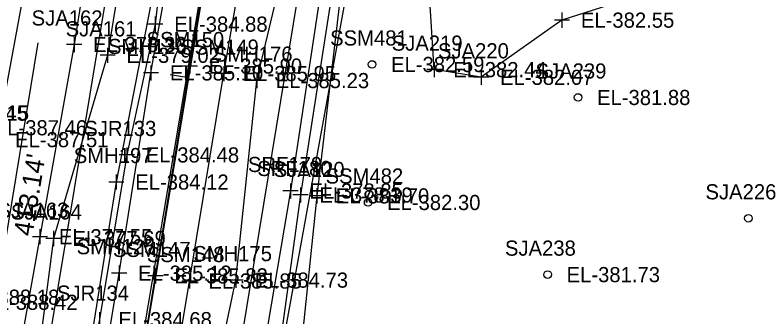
# Model space of a CAD drawing. Extents: x 1189978 to 1314812, y 571533 to 629339.
# Drawn here: x 1217588.4 to 1217785.8, y 621960.6 to 622040.1 of the extents above; entities that cross this region are included whole.
import ezdxf

# ---------------------------------------------------------------- set-up
doc = ezdxf.new("R2010")
doc.units = 0
for name, color, linetype in [('SURVEY - CENTERLINE - Preliminary', 7, 'Continuous'), ('SURVEY - CENTERLINE - Preliminary Text', 7, 'Continuous'), ('SURVEY - DRAINAGE - Area Shapes', 7, 'Continuous'), ('SURVEY - DTM - Breaklines', 7, 'Continuous'), ('SURVEY - DTM - Breaklines - Points - Elevations', 7, 'Continuous'), ('SURVEY - DTM - Breaklines - Points - Locators', 7, 'Continuous'), ('SURVEY - DTM - Breaklines - Points - Numbers', 7, 'Continuous'), ('SURVEY - DTM - Spot Points - Elevations', 7, 'Continuous'), ('SURVEY - DTM - Spot Points - Locators', 7, 'Continuous'), ('SURVEY - DTM - Spot Points - Point Numbers', 7, 'Continuous'), ('SURVEY - PROPERTY - ROW Lines', 7, 'Continuous'), ('SURVEY - PROPERTY - ROW Lines Text', 7, 'Continuous'), ('SURVEY - TRANSPORTATION - Roads', 7, 'Continuous'), ('SURVEY - TRANSPORTATION - Roads - Points - Elevations', 7, 'Continuous'), ('SURVEY - TRANSPORTATION - Roads - Points - Locators', 7, 'Continuous'), ('SURVEY - TRANSPORTATION - Roads - Points - Numbers', 7, 'Continuous'), ('SURVEY - UTILITIES - Electric (Overhead) with Text', 7, 'Continuous'), ('SURVEY - VEGETATION - Features - Points - Elevations', 7, 'Continuous'), ('SURVEY - VEGETATION - Features - Points - Locators', 7, 'Continuous'), ('SURVEY - VEGETATION - Features - Points - Numbers', 7, 'Continuous'), ('SURVEY - VEGETATION - Features with Text', 7, 'Continuous')]:
    doc.layers.add(name, color=color, linetype=linetype)

msp = doc.modelspace()

# ---------------------------------------------------------------- linework, layer by layer
at = {"layer": 'SURVEY - CENTERLINE - Preliminary'}
msp.add_line((1217525.37, 621363.65), (1217649.69, 622116.55), dxfattribs=at)
msp.add_line((1217525.37, 621363.65), (1217649.69, 622116.55), dxfattribs=at)
at = {"layer": 'SURVEY - CENTERLINE - Preliminary Text'}
msp.add_line((1217634.33, 622023.52), (1217629.4, 622024.34), dxfattribs=at)
at = {"layer": 'SURVEY - DRAINAGE - Area Shapes'}
msp.add_line((1217415.87, 620731.68), (1218149.36, 625079.9), dxfattribs=at)
at = {"layer": 'SURVEY - DTM - Breaklines'}
for points in [[(1217591.74, 621765.73), (1217601.34, 621822.74), (1217608.84, 621869.52), (1217625.54, 621971.19), (1217634.6, 622026.63), (1217643.17, 622076.74), (1217651.21, 622124.47), (1217659.56, 622173.57), (1217668.17, 622224.78), (1217678.08, 622282.54), (1217688.16, 622340.37), (1217697.26, 622392.62), (1217705.46, 622440.01), (1217714.49, 622490.86), (1217723.28, 622541.33), (1217731.44, 622588.51), (1217739.96, 622637.78), (1217748.52, 622688.04), (1217748.57, 622688.21), (1217756.95, 622738.51)], [(1217685.05, 622529.18), (1217678.55, 622499.44), (1217670.66, 622464.16), (1217662, 622418.29), (1217653.65, 622375.31), (1217647.46, 622326.5), (1217637.7, 622278.06), (1217624.97, 622233.51), (1217617.77, 622187.81), (1217609.29, 622147.05), (1217599.66, 622101.36), (1217592.56, 622056.45), (1217583.44, 622007.19), (1217575.28, 621964.22), (1217564.77, 621919.14), (1217554.54, 621865.01), (1217546.46, 621821.67), (1217537.02, 621781.08), (1217528.09, 621784.53), (1217517.71, 621784.08)], [(1217696.43, 622511.42), (1217690.45, 622501.14), (1217682.75, 622461.47), (1217672.56, 622421.42), (1217668.77, 622381.8), (1217659.15, 622328.76), (1217653.09, 622287.28), (1217639.42, 622228.14), (1217631.31, 622175.39), (1217620.6, 622119.17), (1217610.69, 622074.17), (1217604.05, 622032.34), (1217595.02, 621981.54), (1217586.73, 621935.16), (1217578.82, 621892.7), (1217571.48, 621848.7), (1217561.74, 621801.1), (1217546.07, 621743.68), (1217517.89, 621741.61)], [(1217697.46, 622510.95), (1217695.23, 622500.63), (1217687.54, 622460.4), (1217680.36, 622419.79), (1217673.4, 622382.01), (1217663.19, 622329.29), (1217655.83, 622286.39), (1217645.17, 622227.36), (1217637.36, 622175.23), (1217627.75, 622118.91), (1217619.76, 622071.57), (1217612.88, 622029.47), (1217598.58, 621981.08), (1217592.58, 621934.99), (1217582.82, 621892.2), (1217576.26, 621849.18), (1217566.85, 621799.58), (1217549.42, 621742.26), (1217567.14, 621728.67)], [(1217704.42, 622509.33), (1217700.3, 622496.16), (1217691.81, 622446.34), (1217683.59, 622396.11), (1217675.05, 622345.79), (1217666.22, 622294.23), (1217657.54, 622241.9), (1217648.88, 622192.24), (1217640.73, 622142.53), (1217632.56, 622094.35), (1217625.38, 622048.54), (1217615.19, 621995.99), (1217607.27, 621946.79), (1217598.3, 621895.28), (1217589.38, 621843.86), (1217580.22, 621794.45), (1217573.72, 621781.31), (1217574.43, 621774.4), (1217580.6, 621768.52)], [(1217604.56, 621765.51), (1217608.59, 621775.31), (1217618.98, 621822.73), (1217628.13, 621872.31), (1217636.41, 621920.88), (1217646.75, 621970.08), (1217652.31, 622022.79), (1217663.53, 622069.73), (1217672.49, 622118.54), (1217678.26, 622168.97), (1217683.24, 622219.55), (1217691.94, 622272.25), (1217701.2, 622320.93), (1217709.61, 622368.48), (1217718.57, 622415.45), (1217724.25, 622459.08), (1217730.45, 622491.37), (1217730.86, 622507.08)], [(1217734.86, 622491.68), (1217727.91, 622445.78), (1217720.64, 622398.43), (1217714.5, 622352.23), (1217706.13, 622302.11), (1217699.65, 622260.42), (1217693, 622212.18), (1217687.82, 622174.51), (1217684.08, 622136.25), (1217675.85, 622096.46), (1217671.96, 622067.67), (1217669.46, 622048.53), (1217661.22, 621993.63), (1217653.56, 621948.52), (1217646.28, 621917), (1217643.83, 621906.18), (1217644.06, 621905.86), (1217641.41, 621873.35), (1217633.96, 621824.29), (1217625.6, 621785.71), (1217619.08, 621762.41), (1217607.58, 621724.78)], [(1217697.47, 622046.01), (1217672.43, 622047.59), (1217663.85, 621992.57), (1217657.77, 621948.36), (1217649.39, 621917), (1217667.32, 621906.97), (1217691.53, 621893.28), (1217727.19, 621910.94), (1217768.29, 621913.65), (1217812.92, 621906.99)], [(1217688.16, 622042.74), (1217674.29, 622044.09), (1217668.19, 621992.33), (1217663.38, 621946.61), (1217653.5, 621919.01), (1217672.39, 621908.83), (1217708.13, 621910.46), (1217733.66, 621916.96), (1217767.69, 621917.46), (1217813.77, 621911.49)]]:
    msp.add_lwpolyline(points, dxfattribs=at)
at = {"layer": 'SURVEY - DTM - Breaklines - Points - Locators'}
for p, q in [((1217604.05, 622034.34), (1217604.05, 622030.34)), ((1217606.05, 622032.34), (1217602.05, 622032.34)), ((1217612.88, 622031.47), (1217612.88, 622027.47)), ((1217614.88, 622029.47), (1217610.88, 622029.47)), ((1217634.6, 622028.63), (1217634.6, 622024.63)), ((1217636.6, 622026.63), (1217632.6, 622026.63)), ((1217652.31, 622024.79), (1217652.31, 622020.79)), ((1217654.31, 622022.79), (1217650.31, 622022.79)), ((1217615.19, 621997.99), (1217615.19, 621993.99)), ((1217617.19, 621995.99), (1217613.19, 621995.99)), ((1217661.22, 621995.63), (1217661.22, 621991.63)), ((1217663.85, 621994.57), (1217663.85, 621990.57)), ((1217663.22, 621993.63), (1217659.22, 621993.63)), ((1217665.85, 621992.57), (1217661.85, 621992.57)), ((1217668.19, 621994.33), (1217668.19, 621990.33)), ((1217670.19, 621992.33), (1217666.19, 621992.33)), ((1217595.02, 621983.54), (1217595.02, 621979.54)), ((1217598.58, 621983.08), (1217598.58, 621979.08)), ((1217597.02, 621981.54), (1217593.02, 621981.54)), ((1217600.58, 621981.08), (1217596.58, 621981.08)), ((1217625.54, 621973.19), (1217625.54, 621969.19)), ((1217627.54, 621971.19), (1217623.54, 621971.19)), ((1217646.75, 621972.08), (1217646.75, 621968.08)), ((1217648.75, 621970.08), (1217644.75, 621970.08))]:
    msp.add_line(p, q, dxfattribs=at)
at = {"layer": 'SURVEY - DTM - Spot Points - Locators'}
for centre in [(1217682.78, 622027.05), (1217737.21, 622018.33), (1217681.73, 621990.58), (1217782.22, 621986.41), (1217729.17, 621971.53)]:
    msp.add_circle(centre, 1, dxfattribs=at)
at = {"layer": 'SURVEY - PROPERTY - ROW Lines'}
for p, q in [((1217557.72, 621713), (1217625.03, 622120.62)), ((1217606.4, 621700.95), (1217674.36, 622112.48))]:
    msp.add_line(p, q, dxfattribs=at)
at = {"layer": 'SURVEY - PROPERTY - ROW Lines Text'}
msp.add_line((1217594.47, 622032.76), (1217583.45, 621966.01), dxfattribs=at)
at = {"layer": 'SURVEY - TRANSPORTATION - Roads'}
for points in [[(1217582.48, 621767.23), (1217583.27, 621767.61), (1217591.48, 621818.57), (1217599.69, 621870.76), (1217607.53, 621920.91), (1217615.95, 621971.91), (1217624.34, 622024.82), (1217633.57, 622076.49), (1217641.88, 622125.54), (1217650.64, 622175.68), (1217659.24, 622225.33), (1217669.03, 622282.56), (1217679.25, 622341.35), (1217687.87, 622391.11), (1217696.47, 622441.53), (1217705.33, 622491.37), (1217713.95, 622541.79), (1217722.13, 622587.98), (1217731.03, 622638.52), (1217739.75, 622690.1), (1217739.95, 622691.24)], [(1217602.44, 621764.03), (1217601.61, 621764.4), (1217609.73, 621817.52), (1217617.85, 621867.88), (1217626.38, 621920.56), (1217634.53, 621969.83), (1217643.58, 622024.64), (1217652.44, 622075.54), (1217660.7, 622123.44), (1217668.82, 622172.59), (1217677.49, 622224.09), (1217697.4, 622338.83), (1217706.31, 622389.43), (1217714.67, 622438.11), (1217723.73, 622488.94), (1217732.47, 622539.47), (1217740.61, 622586), (1217749.34, 622636.23), (1217757.51, 622686.56)]]:
    msp.add_lwpolyline(points, dxfattribs=at)
at = {"layer": 'SURVEY - TRANSPORTATION - Roads - Points - Locators'}
for p, q in [((1217624.34, 622026.82), (1217624.34, 622022.82)), ((1217643.58, 622026.64), (1217643.58, 622022.64)), ((1217626.34, 622024.82), (1217622.34, 622024.82)), ((1217645.58, 622024.64), (1217641.58, 622024.64)), ((1217615.95, 621973.91), (1217615.95, 621969.91)), ((1217617.95, 621971.91), (1217613.95, 621971.91)), ((1217634.53, 621971.83), (1217634.53, 621967.83)), ((1217636.53, 621969.83), (1217632.53, 621969.83))]:
    msp.add_line(p, q, dxfattribs=at)
at = {"layer": 'SURVEY - UTILITIES - Electric (Overhead) with Text'}
msp.add_lwpolyline([(1217806.14, 622777), (1217743.09, 622422.64), (1217688.2, 622113.29), (1217626.83, 621775.19), (1217569.14, 621442.23), (1217508.83, 621100.02), (1217448.24, 620751.9)], dxfattribs=at)
at = {"layer": 'SURVEY - VEGETATION - Features - Points - Locators'}
for p, q in [((1217732.95, 622040.76), (1217732.95, 622036.76)), ((1217625.49, 622039.7), (1217625.49, 622035.7)), ((1217734.95, 622038.76), (1217730.95, 622038.76)), ((1217627.49, 622037.7), (1217623.49, 622037.7)), ((1217699.22, 622027.69), (1217699.22, 622023.69)), ((1217701.22, 622025.69), (1217697.22, 622025.69)), ((1217711.59, 622025.66), (1217711.59, 622021.66)), ((1217713.59, 622023.66), (1217709.59, 622023.66)), ((1217617.96, 622005.15), (1217617.96, 622001.15)), ((1217619.96, 622003.15), (1217615.96, 622003.15)), ((1217610.75, 621961.64), (1217610.75, 621957.64))]:
    msp.add_line(p, q, dxfattribs=at)
at = {"layer": 'SURVEY - VEGETATION - Features with Text'}
for points in [[(1217702.96, 622509.49), (1217699.51, 622493.95), (1217693.48, 622453.44), (1217687.22, 622414.99), (1217679.9, 622375.82), (1217673.76, 622340.63), (1217665.91, 622295.21), (1217658.91, 622253.42), (1217654.9, 622206.36), (1217645.64, 622163.87), (1217637.41, 622119.23), (1217630.2, 622079.47), (1217625.49, 622037.7), (1217617.96, 622003.15), (1217610.75, 621959.64), (1217601.11, 621912.04), (1217596.35, 621872.4), (1217583.12, 621827.95), (1217575.08, 621774.11)], [(1217809.21, 622052.52), (1217788.75, 622054.38), (1217753.62, 622045.49), (1217732.95, 622038.76), (1217711.59, 622023.66), (1217699.22, 622025.69), (1217697.28, 622056.62), (1217710.52, 622083.06), (1217734.69, 622089.28), (1217769.88, 622089.01), (1217801.2, 622098.03)]]:
    msp.add_lwpolyline(points, dxfattribs=at)

# ---------------------------------------------------------------- texts
at = {"layer": 'SURVEY - DTM - Breaklines - Points - Elevations'}
for s, p in [('EL-378.33', (1217609.05, 622030.34)), ('EL-379.02', (1217617.88, 622027.47)), ('EL-385.90', (1217639.6, 622024.63)), ('EL-385.23', (1217657.31, 622020.79)), ('EL-382.15', (1217567.45, 622012.24)), ('EL-387.46', (1217582.79, 622008.33)), ('EL-387.51', (1217588.44, 622005.19)), ('EL-384.12', (1217620.19, 621993.99)), ('EL-378.85', (1217666.22, 621991.63)), ('EL-378.39', (1217668.85, 621990.57)), ('EL-381.70', (1217673.19, 621990.33)), ('EL-377.55', (1217600.02, 621979.54)), ('EL-377.69', (1217603.58, 621979.08)), ('EL-385.83', (1217630.54, 621969.19)), ('EL-384.73', (1217651.75, 621968.08)), ('EL-388.18', (1217575.45, 621963.56)), ('EL-388.42', (1217580.28, 621962.22))]:
    msp.add_text(s, height=4, dxfattribs=at).set_placement(p)
at = {"layer": 'SURVEY - DTM - Breaklines - Points - Numbers'}
for s, p in [('SJA162', (1217592.81, 622037.34)), ('SJA161', (1217601.8, 622034.47)), ('SSM150', (1217623.18, 622031.63)), ('SMH176', (1217640.96, 622027.79)), ('SRF245', (1217572.2, 622012.19)), ('SMH197', (1217603.95, 622000.99)), ('SRF179', (1217649.96, 621998.63)), ('SRF180', (1217652.44, 621997.57)), ('SJA120', (1217656.78, 621997.33)), ('SJA163', (1217583.78, 621986.54)), ('SJA164', (1217587.34, 621986.08)), ('SSM147', (1217614.3, 621976.19)), ('SMH175', (1217635.51, 621975.08))]:
    msp.add_text(s, height=4, dxfattribs=at).set_placement(p)
at = {"layer": 'SURVEY - DTM - Spot Points - Elevations'}
for s, p in [('EL-382.59', (1217687.78, 622025.05)), ('EL-381.88', (1217742.21, 622016.33)), ('EL-382.30', (1217686.73, 621988.58)), ('EL-381.73', (1217734.17, 621969.53))]:
    msp.add_text(s, height=4, dxfattribs=at).set_placement(p)
at = {"layer": 'SURVEY - DTM - Spot Points - Point Numbers'}
for s, p in [('SSM481', (1217671.69, 622032.05)), ('SJA239', (1217725.96, 622023.33)), ('SSM482', (1217670.49, 621995.58)), ('SJA226', (1217770.87, 621991.41)), ('SJA238', (1217717.88, 621976.53))]:
    msp.add_text(s, height=4, dxfattribs=at).set_placement(p)
at = {"layer": 'SURVEY - PROPERTY - ROW Lines Text'}
msp.add_text("413.14'", height=5, rotation=80.6236, dxfattribs=at).set_placement((1217592.97, 621981.49))
at = {"layer": 'SURVEY - TRANSPORTATION - Roads - Points - Elevations'}
for s, p in [('EL-385.10', (1217629.34, 622022.82)), ('EL-385.95', (1217648.58, 622022.64)), ('EL-385.12', (1217620.95, 621969.91)), ('EL-385.85', (1217639.53, 621967.83))]:
    msp.add_text(s, height=4, dxfattribs=at).set_placement(p)
at = {"layer": 'SURVEY - TRANSPORTATION - Roads - Points - Numbers'}
for s, p in [('SMH126', (1217612.99, 622029.82)), ('SSM149', (1217632.33, 622029.64)), ('SMH125', (1217604.71, 621976.91)), ('SSM148', (1217623.25, 621974.83))]:
    msp.add_text(s, height=4, dxfattribs=at).set_placement(p)
at = {"layer": 'SURVEY - VEGETATION - Features - Points - Elevations'}
for s, p in [('EL-382.55', (1217737.95, 622036.76)), ('EL-384.88', (1217630.49, 622035.7)), ('EL-382.44', (1217704.22, 622023.69)), ('EL-382.07', (1217716.59, 622021.66)), ('EL-384.48', (1217622.96, 622001.15)), ('EL-384.68', (1217615.75, 621957.64))]:
    msp.add_text(s, height=4, dxfattribs=at).set_placement(p)
at = {"layer": 'SURVEY - VEGETATION - Features - Points - Numbers'}
for s, p in [('SJA219', (1217687.96, 622030.69)), ('SJA220', (1217700.18, 622028.66)), ('SJR133', (1217606.72, 622008.15)), ('SJR134', (1217599.51, 621964.64))]:
    msp.add_text(s, height=4, dxfattribs=at).set_placement(p)

doc.saveas('drawing.dxf')
